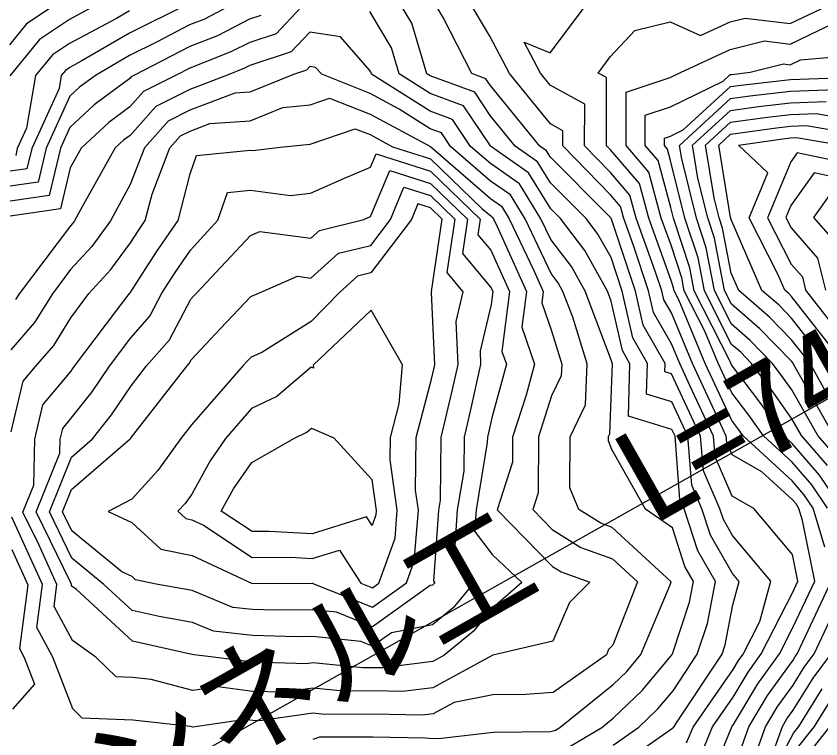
# Model space of a CAD drawing. Extents: x 42655 to 43811, y -141820 to -141156.
# Drawn here: x 42885.9 to 42954.1, y -141680.3 to -141619.1 of the extents above; entities that cross this region are included whole.
import ezdxf

# ---------------------------------------------------------------- set-up
doc = ezdxf.new("R2010")
doc.units = 0
for name, color, linetype in [('D-STR-HTXT', 7, 'Continuous'), ('ZE_HICN', 7, 'Continuous'), ('ZE_LWCN', 7, 'Continuous')]:
    doc.layers.add(name, color=color, linetype=linetype)

msp = doc.modelspace()

# ---------------------------------------------------------------- linework, layer by layer
at = {"layer": 'D-STR-HTXT'}
msp.add_line((43148.457, -141542.195), (42816.396, -141729.579), dxfattribs=at)
at = {"layer": 'ZE_HICN'}
for points in [[(42904.707, -141617.895), (42901.839, -141619.366), (42900.638, -141619.84), (42897.89, -141621.263), (42895.561, -141622.418), (42892.666, -141624.114), (42891.315, -141625.125), (42890.489, -141625.889), (42888.477, -141630.297), (42887.8, -141633.164), (42885.437, -141633.507)], [(42942.742, -141680.693), (42943.296, -141679.342), (42946.688, -141674.471), (42947.142, -141673.716), (42947.542, -141673.159), (42948.948, -141670.392), (42949.893, -141666.986), (42946.635, -141663.097), (42945.864, -141661.768), (42945.564, -141660.843), (42944.169, -141657.642), (42943.937, -141654.688), (42941.482, -141649.411), (42940.907, -141649.235), (42940.928, -141648.54), (42939.069, -141645.285), (42938.412, -141642.389), (42936.388, -141636.303), (42936.364, -141636.236), (42936.356, -141636.207), (42936.332, -141636.178), (42935.999, -141635.835), (42931.22, -141631.04), (42930.886, -141630.5), (42930.319, -141630.101), (42926.103, -141624.938), (42925.741, -141624.395), (42924.564, -141623.965), (42922.13, -141619.198), (42921.311, -141617.818)], [(42955.894, -141660.795), (42954.019, -141657.994), (42951.686, -141655.305), (42950.979, -141654.655), (42948.949, -141651.797), (42946.567, -141648.655), (42946.501, -141648.514), (42946.436, -141648.357), (42943.401, -141642.365), (42943.034, -141640.437), (42941.643, -141636.211), (42941.416, -141635.298), (42940.34, -141631.335), (42939.246, -141630.059), (42939.247, -141627.477), (42941.376, -141626.783), (42945.844, -141624.605), (42946.452, -141624.045), (42946.587, -141624.026), (42948.147, -141623.855), (42950.956, -141623.14), (42951.536, -141623.211), (42952.386, -141622.803), (42956.621, -141622.428)], [(42885.534, -141654.336), (42886.545, -141650.042), (42887.583, -141648.789), (42889.134, -141647.021), (42890.577, -141644.666), (42892.115, -141642.605), (42893.977, -141640.575), (42895.636, -141638.3), (42896.314, -141637.251), (42896.885, -141636.42), (42897.463, -141634.181), (42898.976, -141630.248), (42899.861, -141629.25), (42900.68, -141628.841), (42902.352, -141628.203), (42905.764, -141627.959), (42908.542, -141626.832), (42910.846, -141626.608), (42912.503, -141626.032), (42915.938, -141627.393), (42921.039, -141630.145), (42926.148, -141634.55), (42927.053, -141635.187), (42927.727, -141636.276), (42929.807, -141640.663), (42930.603, -141642.425), (42930.48, -141643.391), (42931.289, -141645.751), (42932.168, -141648.581), (42932.124, -141649.571), (42931.314, -141651.264), (42930.195, -141654.752), (42930.184, -141659.499), (42929.724, -141660.917), (42931.367, -141662.599), (42933.792, -141664.133), (42936.467, -141665.083), (42938.592, -141667.039), (42936.501, -141672.413), (42936.14, -141672.772), (42935.951, -141673.214), (42931.432, -141676.422), (42929.11, -141676.595), (42926.345, -141676.626), (42923.065, -141677.25), (42921.264, -141678.226), (42920.35, -141678.341), (42916.176, -141678.264), (42912.095, -141678.267), (42911.087, -141678.17), (42906.578, -141678.815), (42906.001, -141678.798), (42905.336, -141678.714), (42900.916, -141679.354), (42900.717, -141679.301), (42895.825, -141678.766), (42891.545, -141678.603)], [(42954.613, -141648.476), (42951.637, -141644.682), (42950.585, -141643.6), (42949.121, -141642.339), (42946.509, -141636.28), (42946.495, -141636.205), (42946.489, -141636.188), (42946.481, -141636.155), (42945.471, -141630.03), (42946.476, -141629.105), (42950.355, -141628.546), (42951.561, -141628.414), (42952.906, -141628.366), (42956.652, -141629.015)], [(42916.133, -141669.192), (42919.018, -141667.13), (42919.68, -141665.282), (42920.023, -141660.963), (42919.785, -141659.281), (42919.828, -141654.801), (42921.131, -141649.848), (42921.355, -141648.908), (42921.417, -141648.631), (42921.138, -141642.519), (42921.15, -141642.469), (42921.123, -141642.437), (42922.053, -141636.302), (42921.063, -141635.349), (42919.981, -141635.003), (42919.431, -141636.315), (42916.001, -141640.859), (42914.875, -141641.134), (42913.35, -141642.506), (42910.932, -141644.967), (42906.769, -141647.593), (42905.857, -141647.984), (42905.541, -141648.32), (42905.176, -141648.707), (42900.796, -141653.724), (42899.896, -141654.894), (42897.959, -141657.608), (42895.737, -141660.023), (42893.747, -141661.085), (42895.746, -141661.996), (42898.194, -141664.275), (42900.848, -141664.817), (42905.947, -141667.191), (42911.017, -141667.145), (42911.035, -141667.146), (42911.058, -141667.139), (42911.076, -141667.167), (42916.133, -141669.192)], [(42891.545, -141678.603), (42890.732, -141677.809), (42889.047, -141673.433), (42887.7, -141670.91), (42888.169, -141667.274), (42885.568, -141661.562)], [(42950.146, -141681.323), (42950.861, -141679.307), (42951.256, -141678.651), (42951.792, -141677.904), (42953.483, -141675.195), (42955.013, -141673.124)]]:
    msp.add_lwpolyline(points, dxfattribs=at)
at = {"layer": 'ZE_LWCN'}
for points in [[(42954.459, -141664.11), (42953.477, -141660.806), (42952.685, -141659.625), (42951.701, -141658.49), (42947.541, -141654.671), (42947.103, -141654.055), (42946.589, -141653.377), (42944.331, -141648.524), (42942.081, -141643.132), (42941.697, -141642.373), (42941.65, -141642.129), (42941.445, -141641.507), (42939.544, -141636.221), (42938.747, -141633.284), (42936.305, -141630.437), (42935.953, -141630.075), (42935.961, -141624.294), (42935.269, -141623.915), (42936.268, -141622.532), (42938.372, -141620.299), (42941.343, -141619.589), (42943.939, -141620.737), (42946.431, -141619.582), (42947.718, -141619.255), (42951.52, -141619.719), (42955.824, -141617.657)], [(42889.496, -141617.967), (42886.832, -141619.747), (42885.381, -141621.53)], [(42893.112, -141617.95), (42890.459, -141619.37), (42887.928, -141621.062), (42885.415, -141624.148)], [(42900.498, -141618.074), (42895.553, -141620.528), (42891.463, -141622.924), (42890.478, -141623.451), (42890.12, -141623.691), (42889.764, -141624.128), (42889.574, -141625.234), (42887.26, -141630.302), (42886.853, -141632.027), (42885.431, -141632.233)], [(42910.503, -141617.868), (42907.96, -141620.581), (42905.733, -141621.317), (42904.144, -141622.131), (42900.655, -141623.508), (42899.547, -141624.082), (42896.728, -141625.491), (42895.582, -141626.783), (42893.805, -141628.113), (42891.459, -141630.283), (42890.518, -141631.954), (42889.695, -141635.438), (42885.449, -141636.053)], [(42936.551, -141682.951), (42941.543, -141679.447), (42941.622, -141679.387), (42941.644, -141679.376), (42941.655, -141679.35), (42941.842, -141679.081), (42945.756, -141673.168), (42946.019, -141672.369), (42946.662, -141668.992), (42947.215, -141666.998), (42946.65, -141666.323), (42944.778, -141663.095), (42944.05, -141660.85), (42943.179, -141658.852), (42942.852, -141654.693), (42941.493, -141651.772), (42939.365, -141651.121), (42939.44, -141648.547), (42938.191, -141646.359), (42937.291, -141642.394), (42936.348, -141639.557), (42935.242, -141637.569), (42934.232, -141636.246), (42931.23, -141633.233), (42930.119, -141631.437), (42928.233, -141630.111), (42926.115, -141627.517), (42924.801, -141625.545), (42921.011, -141624.161), (42920.73, -141623.983), (42919.455, -141619.686), (42918.349, -141617.832)], [(42943.84, -141682.011), (42944.938, -141679.334), (42946.699, -141676.805), (42947.965, -141674.703), (42949.08, -141673.152), (42951.745, -141667.904), (42952.183, -141666.975), (42951.73, -141664.73), (42948.441, -141660.83), (42946.619, -141659.782), (42945.16, -141656.431), (42945.022, -141654.683), (42943.028, -141650.396), (42942.162, -141648.534), (42941.47, -141646.878), (42939.947, -141644.211), (42939.533, -141642.383), (42938.256, -141638.543), (42937.424, -141636.231), (42937.153, -141635.232), (42936.323, -141634.264), (42932.266, -141630.092), (42932.268, -141628.81), (42931.207, -141628.229), (42927.733, -141623.951), (42926.084, -141620.801), (42924.304, -141617.804)], [(42944.938, -141683.328), (42946.579, -141679.327), (42946.71, -141679.139), (42948.788, -141675.69), (42950.617, -141673.145), (42951.759, -141670.896), (42953.608, -141666.968), (42952.578, -141661.853), (42952.268, -141660.812), (42952.019, -141660.44), (42951.709, -141660.082), (42949.126, -141657.711), (42946.603, -141656.26), (42946.15, -141655.221), (42946.107, -141654.678), (42945.488, -141653.348), (42943.247, -141648.529), (42941.458, -141644.244), (42940.826, -141643.137), (42940.654, -141642.378), (42940.123, -141640.784), (42938.484, -141636.226), (42937.95, -141634.258), (42936.314, -141632.351), (42934.11, -141630.083), (42934.114, -141626.552), (42931.191, -141624.951), (42930.369, -141623.938), (42928.983, -141621.291), (42931.179, -141622.213), (42934.522, -141617.756)], [(42895.544, -141618.638), (42894.439, -141619.285), (42890.468, -141621.411), (42889.024, -141622.376), (42887.589, -141624.138), (42886.824, -141628.596), (42886.043, -141630.308), (42885.905, -141630.891)], [(42936.541, -141680.883), (42938.706, -141679.363), (42940.326, -141677.795), (42941.608, -141676.268), (42943.654, -141673.178), (42944.514, -141670.563), (42945.191, -141667.008), (42943.693, -141664.423), (42942.535, -141660.857), (42942.189, -141660.063), (42941.767, -141654.698), (42941.504, -141654.133), (42937.822, -141653.007), (42937.952, -141648.554), (42937.312, -141647.433), (42936.365, -141643.257), (42936.041, -141642.4), (42934.117, -141638.944), (42932.067, -141636.256), (42931.24, -141635.426), (42929.353, -141632.375), (42926.148, -141630.121), (42926.127, -141630.095), (42923.86, -141626.695), (42921.018, -141625.657), (42918.396, -141623.994), (42917.74, -141621.783), (42915.897, -141618.695)], [(42906.671, -141619.035), (42905.724, -141619.348), (42902.991, -141620.749), (42900.646, -141621.674), (42895.963, -141624.099), (42895.684, -141624.239), (42895.571, -141624.367), (42892.56, -141626.619), (42890.502, -141628.523), (42889.694, -141630.291), (42888.748, -141634.301), (42885.443, -141634.78)], [(42954.685, -141660.801), (42953.352, -141658.809), (42951.694, -141656.897), (42949.26, -141654.663), (42948.026, -141652.926), (42946.578, -141651.016), (42945.416, -141648.519), (42944.258, -141645.744), (42942.549, -141642.369), (42942.342, -141641.283), (42941.431, -141638.515), (42940.604, -141636.216), (42939.543, -141632.31), (42937.62, -141630.067), (42937.623, -141625.528), (42941.365, -141624.308), (42942.237, -141623.883), (42946.442, -141621.934), (42949.337, -141621.197), (42951.528, -141621.465), (42954.74, -141619.926)], [(42932.792, -141681.012), (42935.573, -141679.378), (42936.53, -141678.603), (42939.004, -141676.209), (42941.54, -141673.187), (42941.593, -141673.061), (42943.009, -141668.758), (42943.341, -141667.016), (42942.607, -141665.75), (42941.543, -141662.474), (42939.259, -141660.873), (42936.424, -141655.811), (42936.125, -141655.083), (42936.127, -141654.725), (42936.234, -141654.501), (42936.4, -141650.762), (42936.464, -141648.56), (42936.434, -141648.507), (42936.389, -141648.308), (42934.156, -141642.409), (42932.993, -141640.319), (42931.252, -141638.037), (42930.412, -141636.263), (42928.586, -141633.312), (42926.134, -141631.587), (42924.442, -141630.129), (42922.92, -141627.845), (42921.025, -141627.153), (42916.062, -141624.005), (42916.025, -141623.88), (42915.921, -141623.705), (42913.427, -141620.859), (42910.817, -141620.454), (42909.248, -141622.128), (42905.742, -141623.285), (42905.296, -141623.514), (42903.908, -141624.062), (42900.663, -141625.299), (42897.773, -141626.744), (42895.593, -141629.2), (42895.05, -141629.606), (42894.333, -141630.269), (42891.551, -141635.212), (42890.876, -141636.448), (42890.718, -141636.665), (42890.541, -141636.858), (42886.186, -141642.633), (42885.885, -141643.123)], [(42911.097, -141680.379), (42911.672, -141680.187), (42916.184, -141680.182), (42920.606, -141680.256), (42921.273, -141680.32), (42921.969, -141680.284), (42926.359, -141679.769), (42931.176, -141679.727), (42931.447, -141679.672), (42931.631, -141679.62), (42932.015, -141679.395), (42936.517, -141675.75), (42937.682, -141674.623), (42938.876, -141673.2), (42941.347, -141667.291), (42941.45, -141667.025), (42936.455, -141662.427), (42935.473, -141662.078), (42933.61, -141660.899), (42932.861, -141659.074), (42932.886, -141654.74), (42934.179, -141652.036), (42934.333, -141648.57), (42933.105, -141644.62), (42932.272, -141642.417), (42931.869, -141641.693), (42931.266, -141640.903), (42929.069, -141636.27), (42927.819, -141634.249), (42926.141, -141633.069), (42922.741, -141630.137), (42921.979, -141628.995), (42921.032, -141628.649), (42918.401, -141626.98), (42915.93, -141625.647), (42911.834, -141624.025), (42911.319, -141623.437), (42910.831, -141623.361), (42910.537, -141623.674), (42909.441, -141624.036), (42905.753, -141625.533), (42904.46, -141625.626), (42900.671, -141627.07), (42898.817, -141627.997), (42896.811, -141630.258), (42895.613, -141633.372), (42893.941, -141636.434), (42892.348, -141638.62), (42890.558, -141640.57), (42889.013, -141642.619), (42887.51, -141645.072), (42885.501, -141647.362)], [(42954.685, -141657.179), (42952.49, -141654.648), (42951.677, -141653.209), (42949.873, -141650.668), (42948.233, -141648.505), (42947.331, -141647.578), (42946.559, -141646.913), (42944.253, -141642.361), (42943.726, -141639.59), (42942.613, -141636.206), (42941.398, -141631.322), (42941.137, -141630.361), (42940.872, -141630.052), (42940.872, -141629.426), (42941.388, -141629.257), (42942.471, -141628.73), (42946.457, -141625.057), (42947.34, -141624.93), (42951.542, -141624.47), (42956.229, -141624.303)], [(42955.352, -141656.364), (42953.858, -141654.642), (42951.665, -141650.764), (42950.796, -141649.539), (42950.006, -141648.497), (42948.144, -141646.584), (42946.551, -141645.211), (42945.106, -141642.357), (42944.419, -141638.744), (42943.582, -141636.202), (42942.332, -141631.178), (42942.146, -141630.046), (42946.461, -141626.069), (42948.094, -141625.834), (42951.547, -141625.456), (42955.398, -141625.319)], [(42955.226, -141654.635), (42951.953, -141648.848), (42951.755, -141648.489), (42951.654, -141648.361), (42948.958, -141645.589), (42946.543, -141643.508), (42945.958, -141642.353), (42945.111, -141637.898), (42944.551, -141636.197), (42943.715, -141632.837), (42943.254, -141630.041), (42946.466, -141627.081), (42948.848, -141626.738), (42951.551, -141626.442), (42954.567, -141626.335)], [(42956.217, -141653.963), (42953.184, -141648.482), (42951.645, -141646.521), (42949.771, -141644.595), (42947.164, -141642.348), (42946.531, -141640.879), (42945.803, -141637.051), (42945.52, -141636.193), (42945.098, -141634.496), (42944.363, -141630.036), (42946.471, -141628.093), (42949.601, -141627.642), (42951.556, -141627.428), (42953.736, -141627.351), (42956.646, -141627.854)], [(42894.42, -141675.088), (42892.708, -141673.416), (42890.705, -141672.01), (42889.162, -141669.122), (42889.401, -141667.268), (42887.852, -141663.866), (42886.509, -141661.119), (42887.43, -141658.844), (42887.533, -141654.952), (42888.217, -141652.048), (42890.598, -141649.175), (42890.76, -141648.971), (42890.892, -141648.773), (42894.488, -141644.016), (42895.552, -141642.589), (42895.607, -141642.53), (42895.655, -141642.464), (42897.842, -141639.083), (42899.681, -141636.407), (42900.697, -141632.471), (42901.235, -141630.897), (42905.776, -141630.453), (42905.997, -141630.483), (42908.319, -141630.204), (42910.862, -141629.958), (42914.672, -141628.634), (42915.946, -141629.138), (42917.839, -141630.159), (42921.044, -141631.186), (42925.412, -141635.391), (42926.155, -141636.031), (42926.286, -141636.124), (42926.384, -141636.282), (42926.686, -141636.92), (42929.178, -141642.432), (42928.794, -141645.453), (42929.868, -141648.591), (42929.149, -141651.217), (42928.011, -141654.763), (42928.006, -141656.887), (42926.695, -141660.931), (42931.382, -141665.727), (42932.111, -141666.188), (42934.559, -141667.057), (42932.817, -141668.786), (42931.412, -141672.072), (42926.329, -141673.259), (42921.253, -141676.009), (42918.677, -141676.335), (42916.166, -141676.289), (42913.712, -141676.291), (42911.077, -141676.038), (42908.554, -141676.399), (42905.99, -141676.324), (42903.031, -141675.949), (42900.901, -141676.257), (42897.394, -141675.315), (42895.808, -141675.141), (42894.42, -141675.088)], [(42956.042, -141648.469), (42951.628, -141642.842), (42951.398, -141642.605), (42951.078, -141642.329), (42950.489, -141640.963), (42948.038, -141636.181), (42949.627, -141632.375), (42947.134, -141630.023), (42951.108, -141629.45), (42951.565, -141629.4), (42952.075, -141629.382), (42955.547, -141629.983)], [(42910.531, -141673.982), (42905.978, -141673.849), (42902.207, -141673.371), (42901.003, -141673.236), (42900.887, -141673.188), (42900.702, -141673.155), (42895.793, -141672.055), (42891.048, -141667.701), (42890.683, -141667.445), (42890.624, -141667.334), (42890.633, -141667.263), (42890.574, -141667.132), (42887.632, -141661.114), (42889.649, -141656.131), (42889.68, -141654.942), (42889.889, -141654.055), (42890.617, -141653.177), (42892.395, -141650.932), (42893.85, -141648.76), (42895.673, -141646.348), (42897.272, -141644.528), (42898.295, -141642.576), (42899.369, -141640.915), (42900.727, -141638.94), (42903.038, -141636.391), (42903.845, -141634.029), (42905.791, -141633.839), (42909.175, -141634.296), (42910.881, -141634.091), (42913.767, -141632.838), (42915.959, -141631.887), (42916.435, -141630.75), (42921.049, -141632.226), (42925.267, -141636.287), (42925.065, -141637.617), (42926.168, -141638.934), (42927.753, -141642.439), (42927.107, -141647.515), (42927.48, -141648.602), (42926.235, -141653.145), (42925.951, -141654.422), (42925.868, -141654.773), (42925.864, -141655.234), (42924.908, -141660.94), (42924.781, -141662.755), (42926.289, -141664.719), (42928.775, -141667.084), (42926.31, -141669.257), (42924.657, -141671.252), (42922.192, -141673.278), (42921.243, -141673.792), (42917.005, -141674.329), (42916.157, -141674.313), (42915.328, -141674.314), (42911.067, -141673.906), (42910.531, -141673.982)], [(42956.664, -141631.632), (42952.126, -141630.671), (42951.575, -141631.441), (42949.599, -141636.174), (42951.615, -141640.108), (42952.557, -141641.188), (42952.831, -141642.321), (42956.738, -141647.355)], [(42895.781, -141669.465), (42893.366, -141667.25), (42890.672, -141665.03), (42888.756, -141661.109), (42890.632, -141656.471), (42892.417, -141654.929), (42894.029, -141652.893), (42895.692, -141650.412), (42896.991, -141648.745), (42898.939, -141646.528), (42900.746, -141643.078), (42900.972, -141642.839), (42901.233, -141642.562), (42905.809, -141637.673), (42906.598, -141637.332), (42910.899, -141637.912), (42911.636, -141637.248), (42915.393, -141636.334), (42915.978, -141636.079), (42917.617, -141632.167), (42921.054, -141633.267), (42924.196, -141636.292), (42923.751, -141639.224), (42926.183, -141642.127), (42926.327, -141642.445), (42926.19, -141643.527), (42925.248, -141647.45), (42925.301, -141648.613), (42924.419, -141652.584), (42923.895, -141654.782), (42923.872, -141657.669), (42923.323, -141660.947), (42923.048, -141664.874), (42924.76, -141667.103), (42922.984, -141669.246), (42921.228, -141670.689), (42917.752, -141671.35), (42916.149, -141672.497), (42915.141, -141672.093), (42911.056, -141671.676), (42909.696, -141671.688), (42905.968, -141671.593), (42902.651, -141671.221), (42900.874, -141670.485), (42898.051, -141669.974), (42895.781, -141669.465)], [(42956.671, -141633.045), (42953.555, -141632.385), (42951.592, -141635.131), (42951.16, -141636.166), (42951.601, -141637.027), (42953.851, -141639.606), (42954.505, -141642.313)], [(42904.299, -141669.206), (42900.862, -141667.782), (42897.806, -141667.229), (42896.068, -141666.875), (42895.768, -141666.595), (42894.908, -141666.203), (42890.661, -141662.704), (42889.879, -141661.103), (42890.645, -141659.21), (42895.617, -141654.914), (42895.664, -141654.855), (42895.713, -141654.782), (42900.429, -141648.729), (42900.606, -141648.527), (42900.77, -141648.214), (42903.257, -141645.579), (42905.833, -141642.849), (42906.559, -141642.538), (42909.776, -141641.145), (42910.915, -141641.298), (42913.256, -141639.191), (42915.99, -141638.525), (42917.652, -141636.323), (42918.799, -141633.585), (42921.058, -141634.308), (42923.124, -141636.297), (42922.437, -141640.831), (42923.8, -141642.457), (42923.193, -141644.984), (42923.359, -141648.622), (42922.887, -141650.746), (42921.923, -141654.791), (42921.88, -141660.105), (42921.738, -141660.955), (42921.316, -141666.993), (42921.413, -141667.119), (42921.312, -141667.24), (42921.213, -141667.322), (42921.016, -141667.359), (42916.141, -141670.844), (42913.078, -141669.618), (42911.046, -141669.41), (42907.822, -141669.44), (42905.957, -141669.392), (42904.299, -141669.206)], [(42954.984, -141634.1), (42953.515, -141636.155), (42955.145, -141638.023)], [(42916.125, -141667.54), (42916.684, -141667.141), (42918.05, -141663.327), (42918.237, -141660.971), (42917.635, -141656.701), (42917.653, -141654.811), (42918.404, -141651.96), (42918.668, -141648.644), (42916.016, -141644.021), (42911.111, -141648.679), (42911.151, -141648.922), (42910.95, -141648.835), (42908.039, -141651.317), (42905.878, -141652.333), (42903.693, -141654.876), (42902.368, -141656.769), (42900.823, -141659.616), (42900.274, -141660.386), (42899.656, -141661.058), (42900.32, -141661.676), (42900.834, -141661.781), (42901.821, -141662.24), (42905.937, -141664.982), (42909.19, -141664.953), (42911.026, -141665.065), (42913.348, -141664.34), (42915.147, -141667.148), (42916.125, -141667.54)], [(42905.927, -141662.773), (42903.325, -141661.041), (42904.352, -141659.149), (42905.899, -141656.937), (42909.524, -141654.849), (42910.572, -141654.356), (42910.974, -141654.014), (42912.871, -141654.833), (42916.083, -141658.359), (42916.452, -141660.979), (42916.421, -141661.372), (42916.101, -141662.265), (42915.637, -141661.541), (42911.016, -141662.983), (42907.362, -141662.761), (42905.927, -141662.773)], [(42885.58, -141664.301), (42886.937, -141667.28), (42886.237, -141672.698), (42886.636, -141673.444), (42887.508, -141675.71), (42885.644, -141677.836)], [(42946.727, -141682.96), (42948.018, -141679.32), (42949.61, -141676.677), (42951.772, -141673.669), (42951.96, -141673.368), (42952.13, -141673.138), (42952.607, -141672.115), (42955.033, -141666.962)], [(42947.641, -141684.386), (42949.439, -141679.313), (42950.433, -141677.664), (42951.782, -141675.787), (42952.722, -141674.281), (42953.572, -141673.131), (42955.958, -141668.018)], [(42948.839, -141685.479), (42951.801, -141679.868), (42952.253, -141679.3), (42954.245, -141676.108)], [(42951.809, -141681.534), (42953.588, -141679.294), (42955.006, -141677.022)], [(42951.817, -141683.2), (42954.924, -141679.288)]]:
    msp.add_lwpolyline(points, dxfattribs=at)

# ---------------------------------------------------------------- texts
at = {"layer": 'D-STR-HTXT'}
msp.add_text('トンネル工\u3000L=748.0m', height=7.96621, rotation=29.51914, dxfattribs=at).set_placement((42885.629, -141693.021))

doc.saveas('drawing.dxf')
